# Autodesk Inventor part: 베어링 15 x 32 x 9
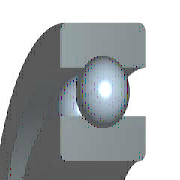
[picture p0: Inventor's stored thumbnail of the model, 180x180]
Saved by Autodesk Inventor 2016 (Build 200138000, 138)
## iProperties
IsCustomPart: 0
Created: 2012-02
Part Number: 베어링 15 x 32 x 9
Material: 강철, 연강
Description: 깊은 그루브 볼 베어링
Document SubType Name: Modeling
Standard: KS B 2023
Designer: mduedu
Standards Organization: KS
Language: ko-KR
Size Designation: 6002 - 15 x 32 x 9
Categories: <MemberInstance><Categories><Category DisplayName="샤프트 부품" InternalName="7f7aeb1f-a693-4053-b835-cee3144e0d98" Mnemonic="SHFT"><Category DisplayName="베어링" Inter
Density: 1 g/cm^3
Appearance: 노란색
Author: mduedu
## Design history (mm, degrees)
sketch "스케치" dims "d0" = 4.42 (= -0.26 x WD + 0.26 x BD)
  geometry: L1 (2.29, 11.75)-(6.71, 11.75); L2 (4.5, 11.75)-(4.5, 9.54); L3 (4.5, 11.75)-(4.5, 13.96); L4 (2.858, 10.271)-(0, 10.271); L5 (0, 7.5)-(9, 7.5); L6 (2.858, 13.229)-(0, 13.229); L7 (0, 16)-(9, 16); L8 (9, 7.5)-(9, 10.271); L9 (6.142, 10.271)-(9, 10.271); L10 (6.142, 13.229)-(9, 13.229); L11 (9, 16)-(9, 13.229); L12 (-1.4, 0)-(8.4, 0) reference; L13 (0, -0.3)-(0, 5.3) reference
  constraints: 22 end point, 4 point on line, 2 collinear, 2 perpendicular, 2 symmetric about line, 1 midpoint, 1 parallel, 14 other
  dimensions: "d9" = 15 diameter of L5 L12 (= WD); "d11" = 32 diameter of L7 L12 (= BD); "d12" = 9 distance between parallel lines of L8 L13 (= KB); "d13" = 20.542 diameter of L9 L12 (= 0.326 x BD + 0.674 x WD)
revolve "본체" stored, may be unused: angle "d6" = 90 deg
revolve "볼" stored, may be unused: angle "d7" = 90 deg
pattern_circular "IDS_ARRAYBALL[SIMPL:T]" dims angle "d3" = 360 deg
body "Solid1"
fillet "모깎기1" dims "d1" = 0.3 (= KRS)
other parameters: "WD" = 15 [user parameter; used in 5 equation terms], "BD" = 32 [user parameter; used in 5 equation terms], "KB" = 9 [user parameter; used in 1 equation term], "KRS" = 0.3 [user parameter; used in 1 equation term], "d4" = 0, "d5" = 0, "d8" = 0, "d14" = 0, "d15" = 0, "BBA" = 0 [user parameter], "BC0" = 2850000 [user parameter], "BC" = 5590000 [user parameter], "BR" = 16 (= 0.5 x BD) [user parameter], "WR" = 7.5 (= 0.5 x WD) [user parameter]
